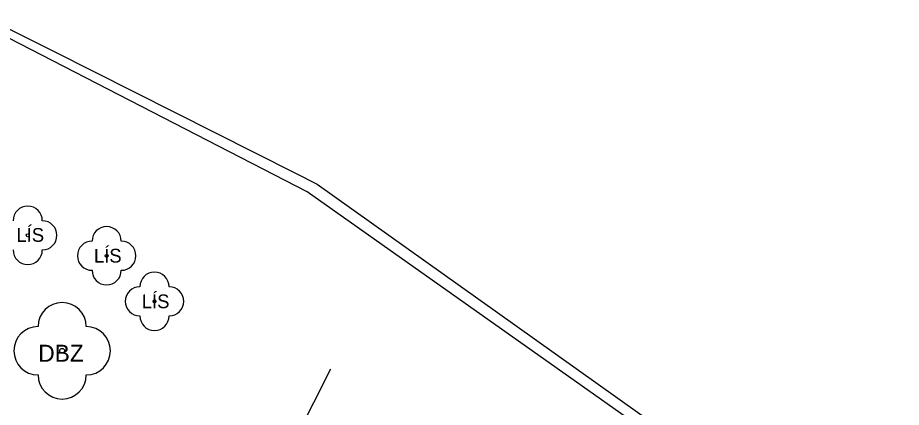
# Model space of a CAD drawing. Extents: x -564037 to -563722, y -1163561 to -1163412.
# Drawn here: x -563870.9 to -563829.28, y -1163483.71 to -1163465.35 of the extents above; entities that cross this region are included whole.
import ezdxf

# ---------------------------------------------------------------- set-up
doc = ezdxf.new("R2010")
doc.units = 0
for name, color, linetype in [('Obvod PU', 7, 'Continuous'), ('Vrstva 1', 7, 'Continuous'), ('Vrstva 2', 7, 'Continuous')]:
    doc.layers.add(name, color=color, linetype=linetype)

msp = doc.modelspace()

# ---------------------------------------------------------------- linework, layer by layer
for points in [[(-563982.839, -1163488.47), (-563983.409, -1163491.846), (-563990.891, -1163500.051), (-563993.495, -1163501.54), (-564001.695, -1163505.76), (-564021.072, -1163514.028), (-564021.939, -1163519.359), (-564028.021, -1163535.92), (-563982.332, -1163543.556), (-563870.708, -1163549.442), (-563829.278, -1163493.346), (-563857.264, -1163473.56), (-563873.956, -1163464.96), (-563885.354, -1163462.845), (-563964.187, -1163417.135), (-563977.612, -1163460.096), (-563977.509, -1163470.055), (-563981.031, -1163479.642), (-563982.839, -1163488.47)], [(-563857.757, -1163485.062), (-563856.157, -1163481.899)]]:
    msp.add_lwpolyline(points)
at = {"layer": 'Obvod PU'}
for p, q in [((-563869.21, -1163466.93), (-563857.82, -1163472.67)), ((-563847.48, -1163479.82), (-563837.86, -1163486.67))]:
    msp.add_line(p, q, dxfattribs=at)
for points in [[(-563885.14, -1163462.32), (-563874.2, -1163464.42), (-563869.21, -1163466.93)], [(-563857.82, -1163472.67), (-563856.79, -1163473.19), (-563847.48, -1163479.82)]]:
    msp.add_lwpolyline(points, dxfattribs=at)
at = {"layer": 'Vrstva 2'}
for centre, radius in [((-563870.427, -1163475.604), 0.0688), ((-563866.709, -1163476.565), 0.0688), ((-563864.455, -1163478.714), 0.0688), ((-563868.804, -1163481.044), 0.114), ((-563868.804, -1163481.044), 0.114)]:
    msp.add_circle(centre, radius, dxfattribs=at)
for centre, radius, start, end in [((-563870.427, -1163474.916), 0.688, 0, 180), ((-563869.739, -1163475.604), 0.688, 270, 90), ((-563866.709, -1163475.877), 0.688, 0, 180), ((-563867.397, -1163476.565), 0.688, 90, 270), ((-563866.021, -1163476.565), 0.688, 270, 90), ((-563870.427, -1163476.292), 0.688, 180, 0), ((-563866.709, -1163477.253), 0.688, 180, 0), ((-563864.455, -1163478.026), 0.688, 0, 180), ((-563865.143, -1163478.714), 0.688, 90, 270), ((-563863.767, -1163478.714), 0.688, 270, 90), ((-563868.804, -1163479.907), 1.137, 0, 180), ((-563868.804, -1163479.907), 1.137, 0, 180), ((-563864.455, -1163479.402), 0.688, 180, 0), ((-563869.942, -1163481.044), 1.137, 90, 270), ((-563869.942, -1163481.044), 1.137, 90, 270), ((-563867.667, -1163481.044), 1.137, 270, 90), ((-563867.667, -1163481.044), 1.137, 270, 90), ((-563868.804, -1163482.181), 1.137, 180, 0), ((-563868.804, -1163482.181), 1.137, 180, 0)]:
    msp.add_arc(centre, radius, start, end, dxfattribs=at)

# ---------------------------------------------------------------- texts
at = {"layer": 'Vrstva 1'}
for s, height, p in [('LÍS', 0.648, (-563870.954, -1163475.912)), ('LÍS', 0.648, (-563867.305, -1163476.89)), ('LÍS', 0.648, (-563865.051, -1163479.04)), ('DBZ', 0.8, (-563869.928, -1163481.56))]:
    msp.add_text(s, height=height, rotation=0.1546, dxfattribs=at).set_placement(p)

doc.saveas('drawing.dxf')
